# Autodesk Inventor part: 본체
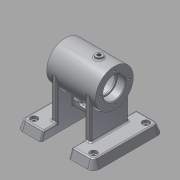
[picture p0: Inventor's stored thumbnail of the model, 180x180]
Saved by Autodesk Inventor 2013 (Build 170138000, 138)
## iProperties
Created: 2016-07
Part Number: 본체
Material: 알루미늄 6061
Document SubType Name: Modeling
Designer: Administrator
Density: 2.71 g/cm^3
Mass: 500.218 g
Surface Area: 539.553 cm^2
Volume: 184.582 cm^3
Author: Administrator
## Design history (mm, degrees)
sketch "스케치1"
  geometry: L1 (0, 0)-(0, 70); C1 r 27 at (0, 70); 1 further point
  constraints: 2 coincident, 2 end point, 1 centre point, 1 vertical
  dimensions: "d0" = 54 diameter of C1; "d15" = 70 distance of L1.start L1.end
extrude "돌출1" new body sketch "스케치1" stored distance "d2" = 70; taper "d3" = 0 deg
sketch "스케치2"
  geometry: L1 (-35, 97)-(-35, 43) reference; L2 (35, 43)-(35, 97) reference; L3 (-35, 86)-(-23, 86); L4 (-23, 86)-(-23, 84); L5 (-23, 84)-(-21, 84); L6 (-21, 84)-(-21, 92); L7 (-21, 92)-(21, 92); L8 (21, 92)-(21, 84); L9 (21, 84)-(23, 84); L10 (23, 84)-(23, 86); L11 (23, 86)-(35, 86); L12 (-35, 70)-(35, 70); 1 further point
  constraints: 20 end point, 5 perpendicular, 4 parallel, 2 midpoint, 2 point on line
  dimensions: "d4" = 32 diameter of L3 L12; "d6" = 28 diameter of L5 L12; "d7" = 44 diameter of L7 L12; "d8" = 28 diameter of L9 L12; "d9" = 32 diameter of L11 L12; "d10" = 12 distance of L3.start L3.end; "d11" = 42 distance of L6.end L7.end; "d12" = 12 distance of L10.end L11.end; "d13" = 2 distance of L8.end L9.end
revolve "회전1" sketch "스케치2" stored, may be unused: angle "d14" = 90 deg
sketch "스케치3"
  geometry: L1 (-55, -50)-(-20, -50); L2 (-20, -50)-(-20, 50); L3 (-20, 50)-(-55, 50); L4 (-55, 50)-(-55, -50); L5 (0, 0)-(-72.5, 0)
  constraints: 10 end point, 2 parallel, 2 perpendicular, 1 horizontal, 1 other
  dimensions: "d16" = 35 distance of L2.end L3.end; "d18" = 100 distance of L3.end L1.start; "d37" = 55 distance from line of L4 L5.start
extrude "돌출2" join sketch "스케치3" distance "d20" = 12; taper "d21" = 0 deg
feature "면 기울기1" dims angle "d22" = -20 deg
fillet "모깎기3" dims "d26" = 10, "d27" = 5, "d28" = 10, "d29" = 5
sketch "스케치5"
  geometry: L1 (-50.632, 41.41)-(-50.632, -41.41) reference; L2 (-46.41, -45.632)-(-20, -45.632) reference; L3 (-20, -45.632)-(-20, 45.632) reference; L4 (-20, 45.632)-(-46.41, 45.632) reference; L5 (-42.5, -37.5)-(-42.5, 37.5); L6 (-42.5, 0)-(0, 0); 5 further points; 2 other entities
  constraints: 4 end point, 3 coincident, 2 perpendicular, 1 midpoint, 2 other
  dimensions: "d34" = 75 distance of L5.start L5.end; "d36" = 42.5 distance from line of L5 point (0, 0)
hole "구멍1" sketch "스케치5" at (-42.5, -37.5), (-42.5, 37.5) diameter "d38" = 6; stored, may be unused: countersink angle "d42" = 90 deg, drill point angle "d44" = 118 deg; dims "d39" = 6, "d40" = 10, "d41" = 4, "d43" = 8
sketch "스케치6"
  geometry: L1 (-12, 4.368)-(-12, 95.632) reference; L2 (0, 50)-(-70, 50); L3 (-12, 23)-(-70, 23); L4 (-12, 77)-(-70, 77); A1 r 27 centre (-70, 50) between (-70, 23) and (-70, 77) reference
  constraints: 6 end point, 2 parallel, 2 point on circle, 2 point on line, 1 perpendicular, 1 other
  dimensions: "d45" = 54 distance between parallel lines of L4 L3
extrude "돌출3" join sketch "스케치6" distance "d46" = 8; taper "d47" = 0 deg
fillet "모깎기4" dims "d48" = 2
fillet "모깎기5" dims "d49" = 2
sketch "스케치7"
  geometry: L1 (-15.325, 22)-(15.005, 22); L2 (35, 43)-(-35, 43) reference; 1 further point
  constraints: 2 end point, 1 horizontal
  dimensions: "d50" = 21 distance between parallel lines of L1 L2
feature "리브1" sketch "스케치7" dims "d51" = 1, "d52" = 8, "d53" = 0, "d54" = 0, "d55" = 1, "d56" = 1
sketch "스케치8"
  geometry: L1 (28, 13.5)-(12, 13.5); L2 (12, 6.5)-(28, 6.5); L3 (12, 10)-(28, 10); L4 (66.555, -22)-(42, -22) reference; L5 (20, -22)-(20, 17.838); A1 r 3.5 centre (12, 10) between (12, 13.5) and (12, 6.5); A2 r 3.5 centre (28, 10) between (28, 6.5) and (28, 13.5)
  constraints: 8 end point, 4 point on circle, 4 tangent, 2 centre point, 2 parallel, 1 horizontal, 1 perpendicular
  dimensions: "d57" = 3.5 radius of A2; "d59" = 23 dimension on A2 A1; "d60" = 32 distance between parallel lines of L3 L4; "d61" = 11.5 dimension on A1 L5
extrude "돌출4" cut sketch "스케치8" stored distance "d62" = 8; taper "d63" = 0 deg
fillet "모깎기6" dims "d64" = 2
fillet "모깎기7" dims "d65" = 2
node "작업 평면2"
  node "작업 평면1"
sketch "스케치9"
  geometry: L1 (-35, 27)-(-35, -27) reference; L2 (-35, 0)-(13, 0); C1 r 5 at (13, 0); 1 further point
  constraints: 2 end point, 1 centre point, 1 coincident, 1 midpoint, 1 perpendicular
  dimensions: "d67" = 48 distance of L2.start L2.end; "d69" = 10 diameter of C1
extrude "돌출5" join sketch "스케치9" stored distance "d70" = 8; taper "d71" = 0 deg
hole "구멍2" diameter "d74" = 5.188; stored, may be unused: countersink angle "d78" = 90 deg, drill point angle "d80" = 118 deg; dims "d72" = 10, "d73" = 10, "d75" = 6, "d76" = 10, "d77" = 4, "d79" = 8
sketch "스케치10"
  geometry: L1 (0, 70)-(0, 51.416); L2 (0, 70)-(-15.898, 44.559); C1 r 14 at (0, 70) reference; 1 further point
  constraints: 4 end point, 1 vertical
  dimensions: "d83" = 30 distance of L1.start L2.end; "d122" = 32 deg angle of L1 L2
node "작업 평면3"
sketch "스케치11"
  geometry: C1 r 6 at (0, 0); 2 further points
  constraints: 1 centre point, 1 coincident
  dimensions: "d84" = 12 diameter of C1
extrude "돌출6" join sketch "스케치11" stored distance "d86" = 8; taper "d87" = 0 deg
hole "구멍3" diameter "d90" = 5.188; stored, may be unused: countersink angle "d94" = 90 deg, drill point angle "d96" = 118 deg; dims "d88" = 10, "d89" = 10, "d91" = 6, "d92" = 10, "d93" = 4, "d95" = 8
fillet "모깎기9" dims "d97" = 2
sketch "스케치12" dims "d98" = 42
  geometry: L1 (0, 0)-(-21, 0); C1 r 27 at (0, 0) reference; 2 further points
  constraints: 2 coincident, 2 end point, 1 horizontal, 1 horizontal alignment, 2 other
hole "구멍4" sketch "스케치12" at (-21, 0) diameter "d100" = 3.242; stored, may be unused: countersink angle "d104" = 90 deg, drill point angle "d106" = 118 deg; dims "d101" = 8, "d102" = 10, "d103" = 4, "d105" = 10
chamfer "모따기1" distance "d110" = 1; stored, may be unused: second distance "d111" = 2, angle "d112" = 45 deg
fillet "모깎기10" dims "d113" = 0.3, "d114" = 3
node "작업 평면5"
sketch "스케치14"
  geometry: L1 (-24.43, 73.457)-(24.43, 73.457); L2 (24.43, 73.457)-(24.43, 66.543); L3 (24.43, 66.543)-(-24.43, 66.543); L4 (-24.43, 66.543)-(-24.43, 73.457); L5 (-24.43, 73.457)-(24.43, 66.543); L6 (-35, 97)-(-35, 43) reference; L7 (35, 43)-(35, 97) reference; L8 (-35, 70)-(35, 70); 2 further points
  constraints: 4 end point, 4 midpoint, 2 other
feature "엠보싱2" sketch "스케치14" dims "d120" = 0.5, "d121" = 0
node "솔리드1"
mirror "대칭1"
pattern_circular "원형 패턴1" dims angle "d108" = 360 deg
mirror "대칭2"
node "투영된 루프1"
other parameters: "d66" = 3
